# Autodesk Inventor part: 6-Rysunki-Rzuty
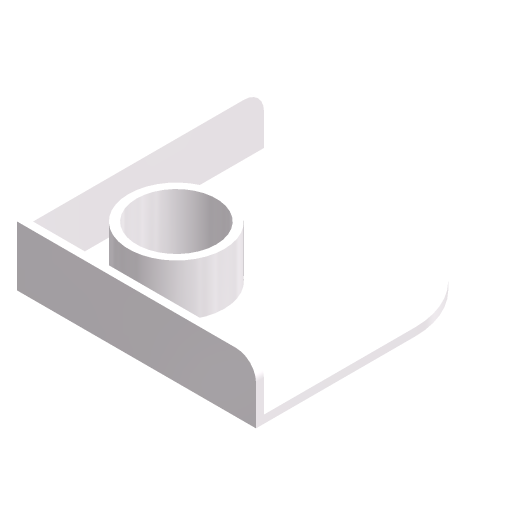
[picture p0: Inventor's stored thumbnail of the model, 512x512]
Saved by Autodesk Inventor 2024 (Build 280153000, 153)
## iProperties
Company: ATC
Shininess: 21.0
Length Units: 11269
Angle Units: 11279
Time Units: 11290
Mass Units: 11283
Length Display Precision: 3
Angle Display Precision: 2
Compacted: True
Created: 2023-03
Part Number: 6-Rysunki-Rzuty
Document SubType Name: Modeling
Designer: Andrzej Jaskulski
Material: Kurs-AJ
Density: 1 g/cm^3
Appearance: Kurs-AJ
Checked By: A.J.
Engr Approved By: Andrzej Jaskulski
Mfg Approved By: Andrzej Jaskulski
Authority: A.J.
Density: 0.0
Volumn: 0.0
Area: 0.0
PropertySet Name: Model Information
Control State: 0
Master: False
Checked Out: False
Title: A.J.: Kurs R2024-MEP
Author: Andrzej Jaskulski
Revision Number: 1/24
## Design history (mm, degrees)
sketch "Szkic1"
  geometry: L1 (0, 0)-(60, 0); L2 (60, 0)-(60, 60); L3 (60, 60)-(0, 60); L4 (0, 60)-(0, 0)
  constraints: 8 end point, 2 parallel, 1 horizontal, 1 perpendicular, 1 other
  dimensions: "d0" = 60 distance of L1.start L1.end (= x); "d1" = 60 distance of L1.end L2.end (= y)
extrude "Baza" new body sketch "Szkic1" distance "d2" = 15 (= h); taper "d3" = 0 deg
sketch "Szkic2"
  geometry: L1 (0, 0)-(0, 60) reference; L2 (60, 0)-(0, 0) reference; 1 further point
  dimensions: "d9" = 20 distance from line of L1 point (20, 20) (= Lx); "d10" = 20 distance from line of L2 point (20, 20) (= Ly)
hole "Otwór" sketch "Szkic2" diameter "d7" = 20 (= d); stored, may be unused: countersink angle "d18" = 60 deg, drill point angle "d20" = 118 deg; dims "d8" = 6, "d16" = 4, "d17" = 2, "d19" = 8
fillet "Zaokrąglenie1" dims "d4" = 20 (= d)
fillet "Zaokrąglenie2" dims "d5" = 5 (= 0.5 x r)
feature "Skorupa1" dims "d6" = 2
node "Bryła1"
node "Korpusy bryłowe"
node "Korpusy powierzchniowe"
node "Początek"
node "Płaszczyzna YZ"
node "Płaszczyzna XZ"
node "Płaszczyzna XY"
node "Oś X"
node "Oś Y"
node "Oś Z"
node "Punkt  środkowy"
other parameters: "inna_glob" = 19 [user parameter], "inna2_glob" = 21 [user parameter], "x" = 60 [user parameter; used in 1 equation term], "y" = 60 [user parameter; used in 1 equation term], "h" = 15 [user parameter; used in 1 equation term], "Lx" = 20 [user parameter; used in 1 equation term], "Ly" = 20 [user parameter; used in 1 equation term], "L2" = 1 [user parameter], "d" = 20 (= 2 x r) [user parameter; used in 2 equation terms], "wys_glob" = 15 [user parameter]
